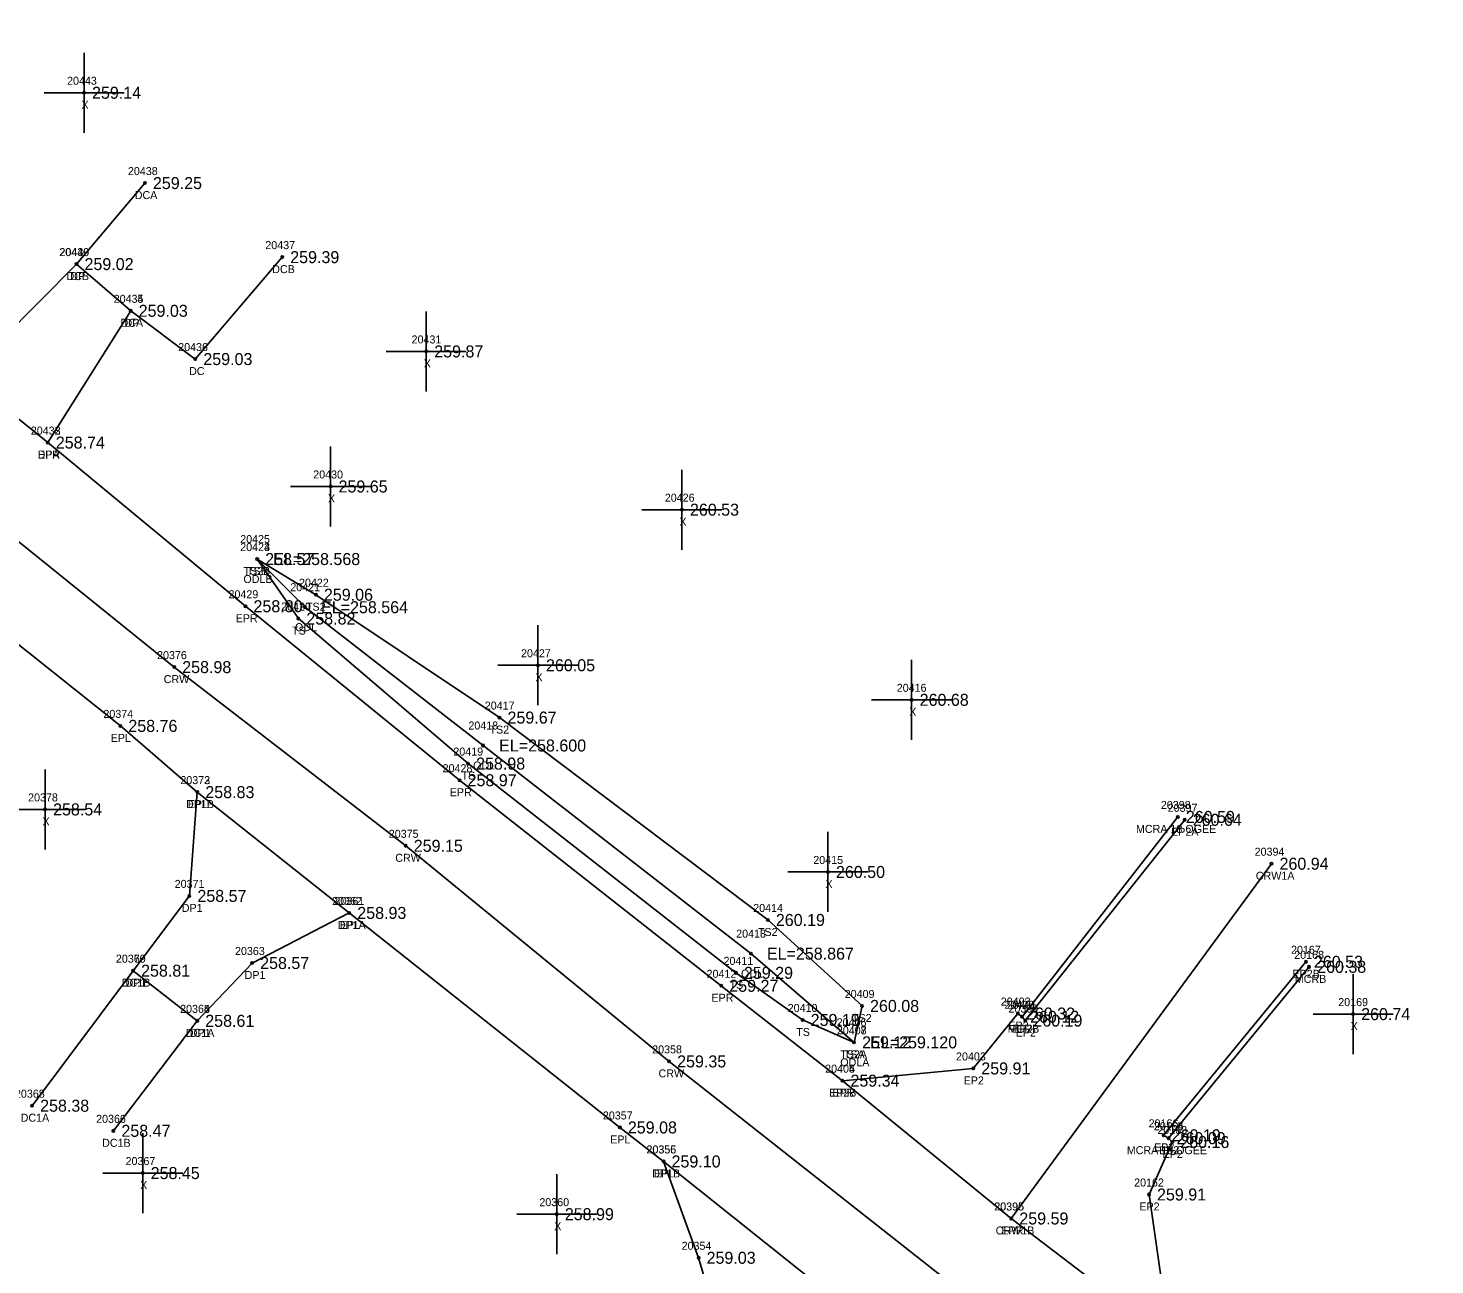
# Model space of a CAD drawing. Extents: x 1961330 to 1962287, y 800294 to 801079.
# Drawn here: x 1961649 to 1961824.8, y 800727.9 to 800882.5 of the extents above; entities that cross this region are included whole.
import ezdxf

# ---------------------------------------------------------------- set-up
doc = ezdxf.new("R2010")
doc.units = 0
for name, color, linetype in [('RD_DTM_BkLn1', 7, 'Continuous'), ('RD_DTM_BkLn2', 7, 'Continuous'), ('RD_DTM_BkLn_txCode', 7, 'Continuous'), ('RD_EX_Conc', 7, 'Continuous'), ('RD_EX_Conc_txCode', 7, 'Continuous'), ('RD_EX_Driveway', 7, 'Continuous'), ('RD_EX_Driveway_txCode', 7, 'Continuous'), ('RD_EX_H2O', 7, 'Continuous'), ('RD_EX_H2O_txCode', 7, 'Continuous'), ('RD_EX_Misc', 7, 'Continuous'), ('RD_EX_Misc_txCode', 7, 'Continuous'), ('RD_EX_Road', 7, 'Continuous'), ('RD_EX_Road_txCode', 7, 'Continuous'), ('RD_EX_TX_Conc_ELEV', 7, 'Continuous'), ('RD_EX_TX_Driveway_ELEV', 7, 'Continuous'), ('RD_EX_TX_H2O_ELEV', 7, 'Continuous'), ('RD_EX_TX_Misc_ELEV', 7, 'Continuous'), ('RD_EX_TX_Road_ELEV', 7, 'Continuous'), ('RD_HC_Survey_ELEV', 7, 'Continuous'), ('RD_HC_Survey_txCode', 7, 'Continuous'), ('RD_SMD_Locator', 7, 'Continuous')]:
    doc.layers.add(name, color=color, linetype=linetype)

msp = doc.modelspace()

# ---------------------------------------------------------------- linework, layer by layer
at = {"layer": 'RD_DTM_BkLn1'}
msp.add_line((1961804.4, 800778.08), (1961771.88, 800733.73), dxfattribs=at)
msp.add_lwpolyline([(1962257.08, 800334.72), (1962203.79, 800372.43), (1962164.31, 800399.58), (1962126.58, 800429.85), (1962084.5, 800463.37), (1962045.12, 800502.48), (1962010.49, 800530.36), (1961971.27, 800562.01), (1961931.18, 800594.14), (1961890.91, 800625.98), (1961844.41, 800662.62), (1961808.07, 800691.13), (1961729.11, 800753.37), (1961696.19, 800780.32), (1961667.25, 800802.66), (1961624.93, 800836.78), (1961588.01, 800866), (1961545.37, 800899.49), (1961472.25, 800957.29), (1961437.91, 800983.99), (1961399.03, 801013.16), (1961365.01, 801035.89)], dxfattribs=at)
at = {"layer": 'RD_DTM_BkLn2'}
for points in [[(1961752.23, 800755.75), (1961753.22, 800760.3), (1961741.45, 800771.05), (1961707.91, 800796.35), (1961684.96, 800811.71), (1961677.62, 800816.17)], [(1961752.23, 800755.75), (1961745.8, 800758.55), (1961737.46, 800764.44), (1961703.98, 800790.6), (1961682.77, 800808.73), (1961677.62, 800816.17)]]:
    msp.add_lwpolyline(points, dxfattribs=at)
at = {"layer": 'RD_EX_Conc'}
for p, q in [((1961663.59, 800863.17), (1961655.04, 800853.04)), ((1961792.69, 800783.93), (1961773.22, 800758.95)), ((1961791.54, 800743.77), (1961809.1, 800765.19)), ((1961649.49, 800747.83), (1961662.11, 800764.71)), ((1961670.13, 800758.44), (1961659.65, 800744.69))]:
    msp.add_line(p, q, dxfattribs=at)
msp.add_lwpolyline([(1961661.81, 800847.2), (1961669.89, 800841.17), (1961680.75, 800853.91)], dxfattribs=at)
at = {"layer": 'RD_EX_Driveway'}
for points in [[(1961651.45, 800830.73), (1961661.81, 800847.2), (1961655.04, 800853.04), (1961641.14, 800839.02)], [(1961689.13, 800771.93), (1961676.99, 800765.67), (1961670.13, 800758.44), (1961662.11, 800764.71), (1961669.15, 800774.06), (1961670.14, 800787.03)], [(1961801.42, 800682.57), (1961792.79, 800679.78), (1961785.2, 800682.11), (1961781.31, 800680.84), (1961776.43, 800674.97), (1961765.27, 800683.8), (1961771.82, 800693.99), (1961761.47, 800704.29), (1961751.75, 800711.21), (1961746.29, 800707.66), (1961742.29, 800702.88), (1961731.89, 800711.6), (1961735.94, 800718.16), (1961732.79, 800728.82), (1961728.41, 800740.86)]]:
    msp.add_lwpolyline(points, dxfattribs=at)
at = {"layer": 'RD_EX_H2O'}
msp.add_lwpolyline([(1961752.23, 800755.75), (1961739.33, 800766.84), (1961705.86, 800792.86), (1961683.6, 800810.15), (1961677.62, 800816.17)], dxfattribs=at)
at = {"layer": 'RD_EX_Misc'}
for p, q in [((1961655.98, 800869.46), (1961655.98, 800879.46)), ((1961650.98, 800874.46), (1961660.98, 800874.46)), ((1961698.75, 800837.12), (1961698.75, 800847.12)), ((1961693.75, 800842.12), (1961703.75, 800842.12)), ((1961686.79, 800820.24), (1961686.79, 800830.24)), ((1961730.71, 800817.34), (1961730.71, 800827.34)), ((1961681.79, 800825.24), (1961691.79, 800825.24)), ((1961725.71, 800822.34), (1961735.71, 800822.34)), ((1961712.72, 800797.89), (1961712.72, 800807.89)), ((1961759.42, 800793.57), (1961759.42, 800803.57)), ((1961707.72, 800802.89), (1961717.72, 800802.89)), ((1961754.42, 800798.57), (1961764.42, 800798.57)), ((1961651.11, 800779.87), (1961651.11, 800789.87)), ((1961646.11, 800784.87), (1961656.11, 800784.87)), ((1961748.96, 800772.05), (1961748.96, 800782.05)), ((1961743.96, 800777.05), (1961753.96, 800777.05)), ((1961814.6, 800754.28), (1961814.6, 800764.28)), ((1961809.6, 800759.28), (1961819.6, 800759.28)), ((1961663.31, 800734.41), (1961663.31, 800744.41)), ((1961658.31, 800739.41), (1961668.31, 800739.41)), ((1961715.07, 800729.27), (1961715.07, 800739.27)), ((1961710.07, 800734.27), (1961720.07, 800734.27))]:
    msp.add_line(p, q, dxfattribs=at)
at = {"layer": 'RD_EX_Road'}
for points in [[(1962276.74, 800366.53), (1962275.76, 800367.28), (1962226.46, 800400.66), (1962183.05, 800429.73), (1962145.98, 800455.38), (1962104.4, 800484.06), (1962056.77, 800517.94), (1962023.95, 800541.05), (1961991.87, 800563.56), (1961983.89, 800569.94), (1961938.77, 800603.67), (1961913.43, 800623.83), (1961897.73, 800636.17), (1961851.62, 800671.61), (1961815.86, 800699.48), (1961795.77, 800715.49), (1961771.88, 800733.73), (1961750.77, 800750.96), (1961735.63, 800762.82), (1961702.92, 800788.52), (1961676.16, 800810.27), (1961651.45, 800830.73), (1961641.14, 800839.02)], [(1962241.79, 800315.68), (1962238.35, 800317.6), (1962189.92, 800352.69), (1962151.64, 800383.49), (1962113.78, 800416.39), (1962074.11, 800451.29), (1962034.78, 800486.96), (1962017.07, 800503.17), (1961999.46, 800519.25), (1961962.48, 800552.12), (1961937.08, 800573.11), (1961923.19, 800584.9), (1961883.07, 800617.43), (1961838.29, 800653.43), (1961801.42, 800682.57), (1961728.41, 800740.86), (1961722.95, 800745.11), (1961689.13, 800771.93), (1961670.14, 800787.03), (1961660.52, 800795.31), (1961637.49, 800813.67)], [(1961793.55, 800783.57), (1961773.63, 800758.47), (1961773.22, 800758.95), (1961772.71, 800759.35), (1961767.13, 800752.49), (1961750.77, 800750.96)], [(1961795.77, 800715.49), (1961790.78, 800725.06), (1961789.09, 800736.73), (1961791.99, 800743.29), (1961791.54, 800743.77), (1961790.92, 800744.13), (1961808.7, 800765.82)]]:
    msp.add_lwpolyline(points, dxfattribs=at)
at = {"layer": 'RD_SMD_Locator'}
for centre in [(1961655.98, 800874.46), (1961663.59, 800863.17), (1961655.04, 800853.04), (1961655.04, 800853.04), (1961680.75, 800853.91), (1961661.81, 800847.2), (1961661.81, 800847.2), (1961698.75, 800842.12), (1961669.89, 800841.17), (1961651.45, 800830.73), (1961651.45, 800830.73), (1961686.79, 800825.24), (1961730.71, 800822.34), (1961677.62, 800816.17), (1961677.62, 800816.17), (1961677.62, 800816.17), (1961684.96, 800811.71), (1961676.16, 800810.27), (1961682.77, 800808.73), (1961683.6, 800810.15), (1961667.25, 800802.66), (1961712.72, 800802.89), (1961759.42, 800798.57), (1961707.91, 800796.35), (1961660.52, 800795.31), (1961705.86, 800792.86), (1961703.98, 800790.6), (1961702.92, 800788.52), (1961670.14, 800787.03), (1961670.14, 800787.03), (1961651.11, 800784.87), (1961792.69, 800783.93), (1961793.55, 800783.57), (1961696.19, 800780.32), (1961748.96, 800777.05), (1961804.4, 800778.08), (1961669.15, 800774.06), (1961689.13, 800771.93), (1961689.13, 800771.93), (1961741.45, 800771.05), (1961739.33, 800766.84), (1961662.11, 800764.71), (1961662.11, 800764.71), (1961676.99, 800765.67), (1961808.7, 800765.82), (1961809.1, 800765.19), (1961737.46, 800764.44), (1961735.63, 800762.82), (1961753.22, 800760.3), (1961772.71, 800759.35), (1961670.13, 800758.44), (1961670.13, 800758.44), (1961745.8, 800758.55), (1961773.22, 800758.95), (1961773.22, 800758.95), (1961773.63, 800758.47), (1961814.6, 800759.28), (1961752.23, 800755.75), (1961752.23, 800755.75), (1961752.23, 800755.75), (1961729.11, 800753.37), (1961767.13, 800752.49), (1961750.77, 800750.96), (1961750.77, 800750.96), (1961649.49, 800747.83), (1961659.65, 800744.69), (1961722.95, 800745.11), (1961790.92, 800744.13), (1961791.54, 800743.77), (1961791.54, 800743.77), (1961791.99, 800743.29), (1961728.41, 800740.86), (1961728.41, 800740.86), (1961663.31, 800739.41), (1961789.09, 800736.73), (1961715.07, 800734.27), (1961771.88, 800733.73), (1961771.88, 800733.73), (1961732.79, 800728.82)]:
    msp.add_circle(centre, 0.15, dxfattribs=at)

# ---------------------------------------------------------------- texts
at = {"layer": 'RD_DTM_BkLn_txCode'}
for s, p in [('20423', (1961675.5, 800817.17)), ('20424', (1961675.5, 800817.17)), ('TS2B', (1961675.9, 800814.17)), ('TSB', (1961676.35, 800814.17)), ('20422', (1961682.85, 800812.71)), ('20420', (1961680.62, 800809.73)), ('TS2', (1961683.72, 800809.71)), ('TS', (1961681.98, 800806.73)), ('20417', (1961706.07, 800797.35)), ('TS2', (1961706.66, 800794.35)), ('20419', (1961702.14, 800791.6)), ('TS', (1961703.18, 800788.6)), ('20414', (1961739.62, 800772.05)), ('TS2', (1961740.21, 800769.05)), ('20411', (1961735.91, 800765.44)), ('TS', (1961736.66, 800762.44)), ('20409', (1961751.06, 800761.3)), ('20410', (1961743.93, 800759.55)), ('20407', (1961750.07, 800756.75)), ('20408', (1961750.07, 800756.75)), ('TS2', (1961751.97, 800758.3)), ('TS', (1961745, 800756.55)), ('TS2A', (1961750.5, 800753.75)), ('TSA', (1961750.95, 800753.75))]:
    msp.add_text(s, height=1, dxfattribs=at).set_placement(p)
at = {"layer": 'RD_EX_Conc_txCode'}
for s, p in [('20438', (1961661.47, 800864.17)), ('DCA', (1961662.32, 800861.17)), ('20439', (1961652.92, 800854.04)), ('20437', (1961678.64, 800854.91)), ('DCB', (1961679.5, 800851.91)), ('DCB', (1961653.78, 800851.04)), ('20435', (1961659.69, 800848.2)), ('DCA', (1961660.54, 800845.2)), ('20436', (1961667.75, 800842.17)), ('DC', (1961669.11, 800839.17)), ('20398', (1961790.57, 800784.93)), ('MCRA 18 OGEE', (1961787.46, 800781.93)), ('20369', (1961659.97, 800765.71)), ('20168', (1961807.24, 800766.19)), ('DC1B', (1961660.7, 800762.71)), ('MCRB', (1961807.31, 800763.19)), ('20365', (1961667.99, 800759.44)), ('20400', (1961771.02, 800759.95)), ('MCRB', (1961771.43, 800756.95)), ('DC1A', (1961668.7, 800756.44)), ('20368', (1961647.35, 800748.83)), ('DC1A', (1961648.06, 800745.83)), ('20366', (1961657.49, 800745.69)), ('20165', (1961789.69, 800744.77)), ('DC1B', (1961658.24, 800742.69)), ('MCRA 18 OGEE', (1961786.31, 800741.77))]:
    msp.add_text(s, height=1, dxfattribs=at).set_placement(p)
at = {"layer": 'RD_EX_Driveway_txCode'}
for s, p in [('20440', (1961652.88, 800854.04)), ('DP', (1961654.26, 800851.04)), ('20434', (1961659.69, 800848.2)), ('DP', (1961661.03, 800845.2)), ('20433', (1961649.33, 800831.73)), ('DPA', (1961650.18, 800828.73)), ('20372', (1961668.02, 800788.03)), ('DP1B', (1961668.72, 800785.03)), ('20371', (1961667.31, 800775.06)), ('20362', (1961686.99, 800772.93)), ('DP1', (1961668.2, 800772.06)), ('DP1A', (1961687.7, 800769.93)), ('20370', (1961659.96, 800765.71)), ('20363', (1961674.85, 800766.67)), ('DP1', (1961661.17, 800762.71)), ('DP1', (1961676.05, 800763.67)), ('20364', (1961667.99, 800759.44)), ('DP1', (1961669.19, 800756.44)), ('20355', (1961726.29, 800741.86)), ('DP1B', (1961726.99, 800738.86)), ('20354', (1961730.67, 800729.82))]:
    msp.add_text(s, height=1, dxfattribs=at).set_placement(p)
at = {"layer": 'RD_EX_H2O_txCode'}
for s, p in [('20425', (1961675.5, 800818.17)), ('ODLB', (1961675.9, 800813.17)), ('20421', (1961681.76, 800812.15)), ('ODL', (1961682.35, 800807.15)), ('20418', (1961704.02, 800794.86)), ('ODL', (1961704.61, 800789.86)), ('20413', (1961737.49, 800768.84)), ('ODL', (1961738.09, 800763.84)), ('20406', (1961750.05, 800757.75)), ('ODLA', (1961750.5, 800752.75))]:
    msp.add_text(s, height=1, dxfattribs=at).set_placement(p)
at = {"layer": 'RD_EX_Misc_txCode'}
for s, p in [('20443', (1961653.86, 800875.46)), ('X', (1961655.66, 800872.46)), ('20431', (1961696.92, 800843.12)), ('X', (1961698.44, 800840.12)), ('20430', (1961684.63, 800826.24)), ('X', (1961686.47, 800823.24)), ('20426', (1961728.57, 800823.34)), ('X', (1961730.39, 800820.34)), ('20427', (1961710.6, 800803.89)), ('X', (1961712.4, 800800.89)), ('20416', (1961757.56, 800799.57)), ('X', (1961759.11, 800796.57)), ('20378', (1961648.99, 800785.87)), ('X', (1961650.79, 800782.87)), ('20415', (1961747.13, 800778.05)), ('X', (1961748.65, 800775.05)), ('20169', (1961812.74, 800760.28)), ('X', (1961814.29, 800757.28)), ('20367', (1961661.17, 800740.41)), ('X', (1961662.99, 800737.41)), ('20360', (1961712.89, 800735.27)), ('X', (1961714.75, 800732.27))]:
    msp.add_text(s, height=1, dxfattribs=at).set_placement(p)
at = {"layer": 'RD_EX_Road_txCode'}
for s, p in [('20432', (1961649.33, 800831.73)), ('EPR', (1961650.22, 800828.73)), ('20429', (1961674.04, 800811.27)), ('EPR', (1961674.93, 800808.27)), ('20374', (1961658.4, 800796.31)), ('EPL', (1961659.31, 800793.31)), ('20428', (1961700.8, 800789.52)), ('20373', (1961668.02, 800788.03)), ('EPL', (1961668.93, 800785.03)), ('EPR', (1961701.69, 800786.52)), ('20397', (1961791.43, 800784.57)), ('EP2A', (1961791.85, 800781.57)), ('20361', (1961687.27, 800772.93)), ('EPL', (1961687.93, 800769.93)), ('20167', (1961806.84, 800766.82)), ('20412', (1961733.79, 800763.82)), ('EP2B', (1961807.02, 800763.82)), ('EPR', (1961734.4, 800760.82)), ('20402', (1961770.56, 800760.35)), ('20401', (1961771.34, 800759.95)), ('20399', (1961771.52, 800759.47)), ('EP2', (1961771.51, 800757.35)), ('EP2', (1961772.01, 800756.95)), ('EP2', (1961772.43, 800756.47)), ('20403', (1961764.97, 800753.49)), ('20404', (1961748.61, 800751.96)), ('20405', (1961748.61, 800751.96)), ('EP2', (1961765.92, 800750.49)), ('EP2B', (1961749.09, 800748.96)), ('EPR', (1961749.54, 800748.96)), ('20357', (1961720.83, 800746.11)), ('20166', (1961789.04, 800745.13)), ('20164', (1961789.69, 800744.77)), ('EPL', (1961721.74, 800743.11)), ('20163', (1961790.13, 800744.29)), ('20356', (1961726.27, 800741.86)), ('EP2', (1961789.72, 800742.13)), ('EP2', (1961790.34, 800741.77)), ('EP2', (1961790.78, 800741.29)), ('EPL', (1961727.2, 800738.86)), ('20162', (1961787.23, 800737.73)), ('20396', (1961769.74, 800734.73)), ('EP2', (1961787.88, 800734.73)), ('EPR', (1961770.65, 800731.73))]:
    msp.add_text(s, height=1, dxfattribs=at).set_placement(p)
at = {"layer": 'RD_EX_TX_Conc_ELEV'}
for s, p in [('259.25', (1961664.59, 800862.42)), ('259.39', (1961681.75, 800853.16)), ('259.02', (1961656.04, 800852.29)), ('259.03', (1961662.81, 800846.45)), ('259.03', (1961670.89, 800840.42)), ('260.59', (1961793.69, 800783.18)), ('258.81', (1961663.11, 800763.96)), ('260.38', (1961810.1, 800764.44)), ('260.12', (1961774.22, 800758.2)), ('258.61', (1961671.13, 800757.69)), ('258.38', (1961650.49, 800747.08)), ('258.47', (1961660.65, 800743.94)), ('260.09', (1961792.54, 800743.02))]:
    msp.add_text(s, height=1.5, dxfattribs=at).set_placement(p)
at = {"layer": 'RD_EX_TX_Driveway_ELEV'}
for s, p in [('259.02', (1961656.04, 800852.29)), ('259.03', (1961662.81, 800846.45)), ('258.74', (1961652.45, 800829.98)), ('258.83', (1961671.14, 800786.28)), ('258.57', (1961670.15, 800773.31)), ('258.93', (1961690.13, 800771.18)), ('258.81', (1961663.11, 800763.96)), ('258.57', (1961677.99, 800764.92)), ('258.61', (1961671.13, 800757.69)), ('259.10', (1961729.41, 800740.11)), ('259.03', (1961733.79, 800728.07))]:
    msp.add_text(s, height=1.5, dxfattribs=at).set_placement(p)
at = {"layer": 'RD_EX_TX_H2O_ELEV'}
for s, p in [('EL=258.568', (1961679.62, 800815.42)), ('EL=258.564', (1961685.6, 800809.4)), ('EL=258.600', (1961707.86, 800792.11)), ('EL=258.867', (1961741.33, 800766.09)), ('EL=259.120', (1961754.23, 800755))]:
    msp.add_text(s, height=1.5, dxfattribs=at).set_placement(p)
at = {"layer": 'RD_EX_TX_Misc_ELEV'}
for s, p in [('259.14', (1961656.98, 800873.71)), ('259.87', (1961699.75, 800841.37)), ('259.65', (1961687.79, 800824.49)), ('260.53', (1961731.71, 800821.59)), ('258.57', (1961678.62, 800815.42)), ('258.57', (1961678.62, 800815.42)), ('259.06', (1961685.96, 800810.96)), ('258.82', (1961683.77, 800807.98)), ('260.05', (1961713.72, 800802.14)), ('260.68', (1961760.42, 800797.82)), ('259.67', (1961708.91, 800795.6)), ('258.98', (1961704.98, 800789.85)), ('258.54', (1961652.11, 800784.12)), ('260.50', (1961749.96, 800776.3)), ('260.19', (1961742.45, 800770.3)), ('259.29', (1961738.46, 800763.69)), ('260.08', (1961754.22, 800759.55)), ('260.74', (1961815.6, 800758.53)), ('259.19', (1961746.8, 800757.8)), ('259.12', (1961753.23, 800755)), ('259.12', (1961753.23, 800755)), ('258.45', (1961664.31, 800738.66)), ('258.99', (1961716.07, 800733.52))]:
    msp.add_text(s, height=1.5, dxfattribs=at).set_placement(p)
at = {"layer": 'RD_EX_TX_Road_ELEV'}
for s, p in [('258.74', (1961652.45, 800829.98)), ('258.80', (1961677.16, 800809.52)), ('258.76', (1961661.52, 800794.56)), ('258.83', (1961671.14, 800786.28)), ('258.97', (1961703.92, 800787.77)), ('260.64', (1961794.55, 800782.82)), ('258.93', (1961690.13, 800771.18)), ('260.53', (1961809.7, 800765.07)), ('259.27', (1961736.63, 800762.07)), ('260.32', (1961773.71, 800758.6)), ('260.12', (1961774.22, 800758.2)), ('260.19', (1961774.63, 800757.72)), ('259.91', (1961768.13, 800751.74)), ('259.34', (1961751.77, 800750.21)), ('259.34', (1961751.77, 800750.21)), ('259.08', (1961723.95, 800744.36)), ('260.19', (1961791.92, 800743.38)), ('260.09', (1961792.54, 800743.02)), ('260.16', (1961792.99, 800742.54)), ('259.10', (1961729.41, 800740.11)), ('259.91', (1961790.09, 800735.98)), ('259.59', (1961772.88, 800732.98))]:
    msp.add_text(s, height=1.5, dxfattribs=at).set_placement(p)
at = {"layer": 'RD_HC_Survey_ELEV'}
for s, p in [('258.98', (1961668.25, 800801.91)), ('259.15', (1961697.19, 800779.57)), ('260.94', (1961805.4, 800777.33)), ('259.35', (1961730.11, 800752.62)), ('259.59', (1961772.88, 800732.98))]:
    msp.add_text(s, height=1.5, dxfattribs=at).set_placement(p)
at = {"layer": 'RD_HC_Survey_txCode'}
for s, p in [('20376', (1961665.11, 800803.66)), ('CRW', (1961665.94, 800800.66)), ('20375', (1961694.07, 800781.32)), ('CRW', (1961694.88, 800778.32)), ('20394', (1961802.29, 800779.08)), ('CRW1A', (1961802.44, 800776.08)), ('20358', (1961726.99, 800754.37)), ('CRW', (1961727.79, 800751.37)), ('20395', (1961769.76, 800734.73)), ('CRW1B', (1961769.93, 800731.73))]:
    msp.add_text(s, height=1, dxfattribs=at).set_placement(p)

doc.saveas('drawing.dxf')
